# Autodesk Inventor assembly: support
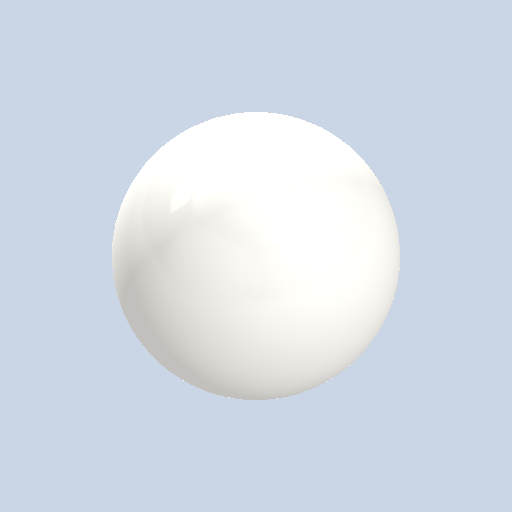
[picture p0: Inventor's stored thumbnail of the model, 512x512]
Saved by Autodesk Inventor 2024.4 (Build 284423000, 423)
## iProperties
Created: 2025-07
Part Number: support
Document SubType Name: Assembly
Designer: AdminForWorker
Title: support v1
Author: AdminForWorker
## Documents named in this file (2)
- c:\worker\convert-fusion-r03-cosv3\tmp\job-1\5\temp\files\c2717cec-cd30-4e2b-a2e5-52afbc4802da\support v1.iam
- c:\worker\convert-fusion-r03-cosv3\tmp\job-1\5\temp\files\c2717cec-cd30-4e2b-a2e5-52afbc4802da\Component1.ipt
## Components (1 placed, 1 different names)
1. Component1:1
